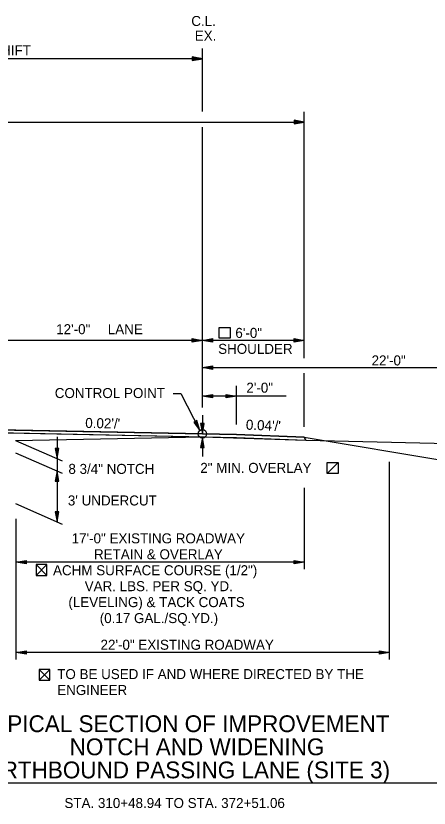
# Model space of a CAD drawing. Extents: x 1398565 to 1398920, y 1968324 to 1968581.
# Drawn here: x 1398842.98 to 1398867.32, y 1968479.6 to 1968526.3 of the extents above; entities that cross this region are included whole.
import ezdxf

# ---------------------------------------------------------------- set-up
doc = ezdxf.new("R2010")
doc.units = 0
for name, color, linetype in [('10', 7, 'Continuous'), ('19', 7, 'Continuous'), ('42', 7, 'Continuous'), ('7', 7, 'Continuous'), ('Level 9', 7, 'Continuous')]:
    doc.layers.add(name, color=color, linetype=linetype)

msp = doc.modelspace()

# ---------------------------------------------------------------- linework, layer by layer
at = {"layer": '10'}
for p, q in [((1398844.173, 1968493.951), (1398844.814, 1968493.31)), ((1398844.814, 1968493.951), (1398844.173, 1968493.31)), ((1398844.554, 1968493.31), (1398844.566, 1968493.31)), ((1398844.345, 1968487.779), (1398844.986, 1968487.138)), ((1398844.986, 1968487.779), (1398844.345, 1968487.138)), ((1398844.727, 1968487.138), (1398844.738, 1968487.138))]:
    msp.add_line(p, q, dxfattribs=at)
for points in [[(1398854.959, 1968507.933), (1398855.601, 1968507.933), (1398855.601, 1968507.292), (1398854.959, 1968507.292)], [(1398861.321, 1968499.966), (1398861.962, 1968499.966), (1398861.962, 1968499.324), (1398861.321, 1968499.324)], [(1398861.321, 1968499.966), (1398861.962, 1968499.966), (1398861.321, 1968499.324)]]:
    msp.add_lwpolyline(points, close=True, dxfattribs=at)
for points in [[(1398844.566, 1968493.31), (1398844.814, 1968493.31), (1398844.814, 1968493.951), (1398844.173, 1968493.951), (1398844.173, 1968493.31), (1398844.554, 1968493.31)], [(1398844.738, 1968487.138), (1398844.986, 1968487.138), (1398844.986, 1968487.779), (1398844.345, 1968487.779), (1398844.345, 1968487.138), (1398844.727, 1968487.138)]]:
    msp.add_lwpolyline(points, dxfattribs=at)
at = {"layer": '19'}
for p, q in [((1398853.969, 1968523.77), (1398829.969, 1968523.77)), ((1398853.369, 1968523.875), (1398853.369, 1968523.665)), ((1398853.969, 1968523.77), (1398853.369, 1968523.875)), ((1398853.809, 1968523.785), (1398853.369, 1968523.82)), ((1398853.369, 1968523.665), (1398853.969, 1968523.77)), ((1398853.369, 1968523.715), (1398853.809, 1968523.755)), ((1398859.969, 1968506.117), (1398859.969, 1968520.64)), ((1398809.969, 1968520.04), (1398859.969, 1968520.04)), ((1398859.369, 1968520.145), (1398859.369, 1968519.935)), ((1398859.969, 1968520.04), (1398859.369, 1968520.145)), ((1398859.809, 1968520.055), (1398859.369, 1968520.09)), ((1398859.369, 1968519.935), (1398859.969, 1968520.04)), ((1398859.369, 1968519.985), (1398859.809, 1968520.025)), ((1398859.969, 1968507.17), (1398804.684, 1968507.17)), ((1398853.369, 1968507.065), (1398853.369, 1968507.275)), ((1398853.369, 1968507.275), (1398853.969, 1968507.17)), ((1398853.369, 1968507.22), (1398853.809, 1968507.185)), ((1398853.969, 1968507.17), (1398853.369, 1968507.065)), ((1398853.809, 1968507.155), (1398853.369, 1968507.115)), ((1398853.969, 1968507.17), (1398854.569, 1968507.275)), ((1398854.569, 1968507.065), (1398853.969, 1968507.17)), ((1398854.129, 1968507.185), (1398854.569, 1968507.22)), ((1398854.569, 1968507.115), (1398854.129, 1968507.155)), ((1398854.569, 1968507.275), (1398854.569, 1968507.065)), ((1398859.369, 1968507.065), (1398859.369, 1968507.275)), ((1398859.369, 1968507.275), (1398859.969, 1968507.17)), ((1398859.369, 1968507.22), (1398859.809, 1968507.185)), ((1398859.969, 1968507.17), (1398859.369, 1968507.065)), ((1398859.809, 1968507.155), (1398859.369, 1968507.115)), ((1398853.969, 1968505.564), (1398854.569, 1968505.669)), ((1398853.969, 1968505.564), (1398875.969, 1968505.564)), ((1398854.569, 1968505.459), (1398853.969, 1968505.564)), ((1398854.129, 1968505.579), (1398854.569, 1968505.614)), ((1398854.569, 1968505.509), (1398854.129, 1968505.549)), ((1398854.569, 1968505.669), (1398854.569, 1968505.459)), ((1398859.969, 1968502.069), (1398859.969, 1968505.245)), ((1398855.969, 1968502.221), (1398855.969, 1968504.482)), ((1398853.969, 1968503.882), (1398854.569, 1968503.987)), ((1398858.895, 1968503.882), (1398853.969, 1968503.882)), ((1398854.569, 1968503.777), (1398853.969, 1968503.882)), ((1398854.129, 1968503.897), (1398854.569, 1968503.932)), ((1398854.569, 1968503.827), (1398854.129, 1968503.867)), ((1398854.569, 1968503.987), (1398854.569, 1968503.777)), ((1398855.369, 1968503.777), (1398855.369, 1968503.987)), ((1398855.369, 1968503.987), (1398855.969, 1968503.882)), ((1398855.369, 1968503.932), (1398855.809, 1968503.897)), ((1398855.969, 1968503.882), (1398855.369, 1968503.777)), ((1398855.809, 1968503.867), (1398855.369, 1968503.827)), ((1398853.646, 1968502.447), (1398853.46, 1968502.352)), ((1398853.761, 1968502.01), (1398853.6, 1968502.418)), ((1398853.824, 1968501.864), (1398853.646, 1968502.447)), ((1398853.969, 1968502.77), (1398853.969, 1968501.661)), ((1398829.969, 1968502.141), (1398855.969, 1968501.621)), ((1398829.969, 1968501.974), (1398855.969, 1968501.454)), ((1398853.46, 1968502.352), (1398853.824, 1968501.864)), ((1398853.502, 1968502.37), (1398853.738, 1968502.001)), ((1398854.074, 1968502.261), (1398853.864, 1968502.261)), ((1398853.864, 1968502.261), (1398853.969, 1968501.661)), ((1398853.919, 1968502.261), (1398853.954, 1968501.821)), ((1398853.969, 1968501.661), (1398854.074, 1968502.261)), ((1398853.984, 1968501.821), (1398854.024, 1968502.261)), ((1398855.969, 1968501.621), (1398859.969, 1968501.461)), ((1398842.969, 1968501.274), (1398845.712, 1968500.064)), ((1398845.41, 1968501.477), (1398845.41, 1968500.201)), ((1398853.969, 1968501.453), (1398853.864, 1968500.853)), ((1398853.954, 1968501.293), (1398853.919, 1968500.853)), ((1398854.074, 1968500.853), (1398853.969, 1968501.453)), ((1398853.969, 1968501.453), (1398853.969, 1968500.332)), ((1398854.024, 1968500.853), (1398853.984, 1968501.293)), ((1398855.969, 1968501.454), (1398860.054, 1968501.291)), ((1398859.969, 1968501.461), (1398875.969, 1968498.794)), ((1398859.969, 1968501.461), (1398860.054, 1968501.291)), ((1398845.515, 1968500.801), (1398845.305, 1968500.801)), ((1398845.305, 1968500.801), (1398845.41, 1968500.201)), ((1398845.36, 1968500.801), (1398845.395, 1968500.361)), ((1398845.41, 1968500.201), (1398845.515, 1968500.801)), ((1398845.425, 1968500.361), (1398845.465, 1968500.801)), ((1398853.864, 1968500.853), (1398854.074, 1968500.853)), ((1398842.969, 1968500.545), (1398845.712, 1968499.335)), ((1398845.41, 1968500.201), (1398845.41, 1968496.469)), ((1398864.993, 1968488.365), (1398864.993, 1968500.015)), ((1398845.41, 1968499.469), (1398845.305, 1968498.869)), ((1398845.395, 1968499.309), (1398845.36, 1968498.869)), ((1398845.515, 1968498.869), (1398845.41, 1968499.469)), ((1398845.465, 1968498.869), (1398845.425, 1968499.309)), ((1398845.305, 1968498.869), (1398845.515, 1968498.869)), ((1398859.969, 1968498.483), (1398859.969, 1968493.687)), ((1398842.969, 1968497.545), (1398845.712, 1968496.335)), ((1398845.515, 1968497.069), (1398845.305, 1968497.069)), ((1398845.305, 1968497.069), (1398845.41, 1968496.469)), ((1398845.36, 1968497.069), (1398845.395, 1968496.629)), ((1398845.41, 1968496.469), (1398845.515, 1968497.069)), ((1398845.425, 1968496.629), (1398845.465, 1968497.069)), ((1398842.993, 1968488.365), (1398842.993, 1968496.656)), ((1398842.993, 1968494.098), (1398843.593, 1968494.203)), ((1398843.593, 1968493.993), (1398842.993, 1968494.098)), ((1398859.969, 1968494.098), (1398842.993, 1968494.098)), ((1398843.153, 1968494.113), (1398843.593, 1968494.148)), ((1398843.593, 1968494.043), (1398843.153, 1968494.083)), ((1398843.593, 1968494.203), (1398843.593, 1968493.993)), ((1398859.369, 1968493.993), (1398859.369, 1968494.203)), ((1398859.369, 1968494.203), (1398859.969, 1968494.098)), ((1398859.369, 1968494.148), (1398859.809, 1968494.113)), ((1398859.969, 1968494.098), (1398859.369, 1968493.993)), ((1398859.809, 1968494.083), (1398859.369, 1968494.043)), ((1398842.993, 1968488.772), (1398843.593, 1968488.877)), ((1398843.593, 1968488.877), (1398843.593, 1968488.667)), ((1398864.393, 1968488.667), (1398864.393, 1968488.877)), ((1398864.393, 1968488.877), (1398864.993, 1968488.772)), ((1398864.993, 1968488.772), (1398842.993, 1968488.772)), ((1398843.593, 1968488.667), (1398842.993, 1968488.772)), ((1398843.153, 1968488.787), (1398843.593, 1968488.822)), ((1398843.593, 1968488.717), (1398843.153, 1968488.757)), ((1398864.393, 1968488.822), (1398864.833, 1968488.787)), ((1398864.993, 1968488.772), (1398864.393, 1968488.667)), ((1398864.833, 1968488.757), (1398864.393, 1968488.717)), ((1398839.453, 1968481.09), (1398868.433, 1968481.09))]:
    msp.add_line(p, q, dxfattribs=at)
msp.add_lwpolyline([(1398852.244, 1968504.041), (1398852.69, 1968504.041), (1398853.824, 1968501.864)], dxfattribs=at)
msp.add_lwpolyline([(1398809.887, 1968501.456), (1398815.969, 1968501.694), (1398829.969, 1968501.974), (1398855.969, 1968501.454), (1398860.054, 1968501.291), (1398859.969, 1968501.461), (1398855.969, 1968501.621), (1398829.969, 1968502.141), (1398815.969, 1968501.861), (1398809.969, 1968501.621)], close=True, dxfattribs=at)
at = {"layer": '42'}
for points in [[(1398842.969, 1968501.274), (1398853.969, 1968501.494)], [(1398853.969, 1968501.494), (1398860.054, 1968501.291), (1398870.969, 1968501.034), (1398879.824, 1968498.574), (1398884.905, 1968499.115), (1398901.722, 1968499.026)]]:
    msp.add_lwpolyline(points, dxfattribs=at)
at = {"layer": '7'}
for p, q in [((1398853.969, 1968520.661), (1398853.969, 1968524.37)), ((1398853.969, 1968503.222), (1398853.969, 1968519.735))]:
    msp.add_line(p, q, dxfattribs=at)
at = {"layer": 'Level 9'}
msp.add_circle((1398853.969, 1968501.661), 0.25, dxfattribs=at)

# ---------------------------------------------------------------- texts
at = {"layer": '10'}
for s, height, p in [('12\'-0" ', 0.59, (1398845.357, 1968507.534)), ('LANE', 0.59, (1398848.395, 1968507.534)), ('6\'-0" ', 0.59, (1398855.91, 1968507.315)), ('SHOULDER', 0.59, (1398854.897, 1968506.375)), ('22\'-0"', 0.59, (1398863.934, 1968505.693)), ('CONTROL POINT', 0.59001, (1398845.274, 1968503.77)), ('2\'-0"', 0.59, (1398856.558, 1968504.086)), ('8 3/4" NOTCH', 0.59001, (1398846.078, 1968499.3)), ('2" MIN. OVERLAY', 0.59001, (1398853.845, 1968499.36)), ("3' UNDERCUT", 0.59001, (1398846.045, 1968497.438)), ('17\'-0" EXISTING ROADWAY', 0.59001, (1398846.269, 1968495.206)), ('RETAIN & OVERLAY', 0.59001, (1398847.584, 1968494.266)), ('ACHM SURFACE COURSE (1/2")', 0.59001, (1398845.173, 1968493.326)), ('VAR. LBS. PER SQ. YD.', 0.59001, (1398847.036, 1968492.386)), ('(LEVELING) & TACK COATS', 0.59001, (1398846.074, 1968491.446)), ('(0.17 GAL./SQ.YD.)', 0.59001, (1398847.923, 1968490.506)), ('22\'-0" EXISTING ROADWAY', 0.59001, (1398847.969, 1968488.934)), ('TO BE USED IF AND WHERE DIRECTED BY THE ', 0.59001, (1398845.418, 1968487.205)), ('ENGINEER', 0.59, (1398845.418, 1968486.265)), ('STA. 310+48.94 TO STA. 372+51.06', 0.59001, (1398845.843, 1968479.606))]:
    msp.add_text(s, height=height, rotation=360, dxfattribs=at).set_placement(p)
at = {"layer": '19'}
msp.add_text('C.L.', height=0.59, dxfattribs=at).set_placement((1398853.314, 1968525.699))
for s, height, rotation, p in [('EX.', 0.59, 360, (1398853.52, 1968524.832)), ("24' SHIFT", 0.59, 360, (1398840.341, 1968523.976)), ("0.02'/'", 0.59, 358.8542, (1398847.065, 1968502.011)), ("0.04'/'", 0.59, 357.7094, (1398856.521, 1968501.91)), ('TYPICAL SECTION OF IMPROVEMENT', 0.98999, 360, (1398840.787, 1968484.079)), ('NOTCH AND WIDENING', 0.98999, 360, (1398846.15, 1968482.718)), ('NORTHBOUND PASSING LANE (SITE 3)', 0.98999, 360, (1398840.16, 1968481.356))]:
    msp.add_text(s, height=height, rotation=rotation, dxfattribs=at).set_placement(p)

doc.saveas('drawing.dxf')
